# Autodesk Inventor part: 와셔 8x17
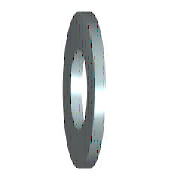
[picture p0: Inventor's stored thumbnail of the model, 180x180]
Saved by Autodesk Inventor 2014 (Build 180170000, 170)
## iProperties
IsCustomPart: 1
Created: 2012-02
Part Number: 와셔 8x17
Material: 강철, 연강
Description: 평면 와셔
Document SubType Name: Modeling
Standard: KS B 1326
Designer: mduedu
Standards Organization: KS
Language: ko-KR
Size Designation: 8x17
Categories: <MemberInstance><Categories><Category DisplayName="조임쇠" InternalName="e4da775c-781d-43d5-af7c-5136215cf5a6" Mnemonic="FSTN"><Category DisplayName="와셔" InternalN
Density: 1 g/cm^3
Appearance: Orange
Author: mduedu
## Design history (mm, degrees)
sketch "스케치"
  geometry: C1 r 8.5 at (0, 0); C2 r 4.2 at (0, 0); 1 further point
  constraints: 2 centre point, 2 coincident
  dimensions: "d0" = 8.4 diameter of C2 (= SD1); "d1" = 17 diameter of C1 (= SD2)
extrude "본체" new body sketch "스케치" distance "d2" = 1.6 (= SD); taper "d3" = 0 deg
workaxis "Work Axis1"
workplane "Work Plane1"
body "Solid1"
other parameters: "SD1" = 8.4 [user parameter; used in 1 equation term], "SD2" = 17 [user parameter; used in 1 equation term], "SD" = 1.6 [user parameter; used in 1 equation term], "d4" = 0, "d5" = 0, "d6" = 0, "d7" = 0, "NND" = 8 [user parameter]
